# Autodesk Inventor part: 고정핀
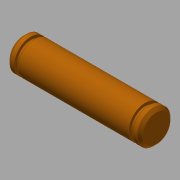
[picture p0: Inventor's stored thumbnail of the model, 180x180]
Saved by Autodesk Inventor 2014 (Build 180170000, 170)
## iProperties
Created: 2015-12
Part Number: 고정핀
Material: 스테인리스강
Document SubType Name: Modeling
Designer: mduedu
Density: 8.08 g/cm^3
Appearance: 주황색
Author: mduedu
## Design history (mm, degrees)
sketch "스케치1"
  geometry: C1 r 3 at (0, 0); 1 further point
  constraints: 1 centre point, 1 coincident
  dimensions: "d0" = 6 diameter of C1
extrude "돌출1" new body sketch "스케치1" stored distance "d1" = 24; taper "d2" = 0 deg
chamfer "모따기1" distance "d3" = 0.5; stored, may be unused: second distance "d4" = 2, angle "d5" = 45 deg
sketch "스케치2"
  geometry: L1 (-12, 2.5)-(-11.5, 3) reference; L2 (-11.5, 3)-(11.5, 3) reference; L3 (11.5, 3)-(12, 2.5) reference; L4 (12, 2.5)-(12, -2.5) reference; L5 (12, -2.5)-(11.5, -3) reference; L6 (11.5, -3)-(-11.5, -3) reference; L7 (-11.5, -3)-(-12, -2.5) reference; L8 (-12, -2.5)-(-12, 2.5) reference; L9 (10, 3)-(10.7, 3); L10 (10.7, 3)-(10.7, 2.5); L11 (10.7, 2.5)-(10, 2.5); L12 (10, 2.5)-(10, 3); L13 (0, 0)-(12, 0)
  constraints: 10 end point, 2 parallel, 1 collinear, 1 horizontal, 1 midpoint, 1 perpendicular
  dimensions: "d6" = 10 distance from line of L12 L13.start; "d7" = 5 diameter of L11 L13; "d8" = 0.7 distance of L9.start L9.end
revolve "회전1" sketch "스케치2" stored, may be unused: angle "d9" = 90 deg
node "솔리드1"
mirror "대칭1"
node "절단 모서리 투영1"
